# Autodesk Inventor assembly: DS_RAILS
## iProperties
Shininess: 64.0
Length Units: 11272
Angle Units: 11279
Time Units: 11290
Mass Units: 11286
Length Display Precision: 3
Angle Display Precision: 2
Compacted: True
Part Number: DS_RAILS
Document SubType Name: Assembly
Created: 2004-08
Designer: John Blackburn
Manufacturer: Standard
Standards Organization: Custom
Density: 0.0
Volumn: 0.0
Area: 0.0
PropertySet Name: Model Information
Control State: 0
Master: False
Checked Out: False
Author: John Blackburn
